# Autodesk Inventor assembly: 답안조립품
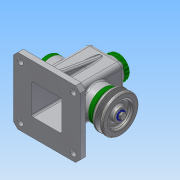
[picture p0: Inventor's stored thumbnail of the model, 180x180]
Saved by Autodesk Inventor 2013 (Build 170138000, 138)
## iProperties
Created: 2018-10
Part Number: 답안조립품
Document SubType Name: Assembly
Designer: Administrator
Author: Administrator
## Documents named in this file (14)
- C:\Users\Administrator\Desktop\481013V1002\답안조립품.iam
- C:\Users\Administrator\Desktop\481013V1002\본체.ipt
- C:\Users\Administrator\Desktop\481013V1002\V-벨트풀리.ipt
- C:\Users\Administrator\Desktop\481013V1002\뒤커버.ipt
- C:\Users\Administrator\Desktop\481013V1002\멈춤링 15 x 1.ipt
- C:\Users\Administrator\Desktop\481013V1002\베어링 15 x 35 x 11.ipt
- C:\Users\Administrator\Desktop\481013V1002\볼트 M4 x 10.ipt
- C:\Users\Administrator\Desktop\481013V1002\볼트 M6 x 12.ipt
- C:\Users\Administrator\Desktop\481013V1002\상부캡.ipt
- C:\Users\Administrator\Desktop\481013V1002\앞커버.ipt
- C:\Users\Administrator\Desktop\481013V1002\오일실 15 25 7.ipt
- C:\Users\Administrator\Desktop\481013V1002\와셔.ipt
- C:\Users\Administrator\Desktop\481013V1002\축.ipt
- C:\Users\Administrator\Desktop\481013V1002\키 5 x 5 x 14.ipt
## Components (1 placed, 1 different names)
1. V-벨트풀리:1 — 플러쉬:1
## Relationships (1: Flush 1)
- 플러쉬:1 [Flush]: V-벨트풀리:1
